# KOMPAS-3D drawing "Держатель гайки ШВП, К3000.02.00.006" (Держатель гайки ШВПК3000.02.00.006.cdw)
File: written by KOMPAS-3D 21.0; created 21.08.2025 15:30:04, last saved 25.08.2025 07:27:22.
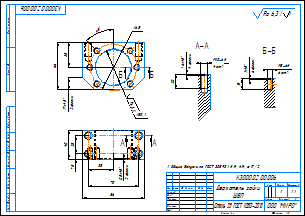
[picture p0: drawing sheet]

Sheet 1: A3, landscape

Document properties: Автор: admin; Знак неуказанной шероховатости: 4; Параметр неуказанной шероховатости: Ra 6,3; Масса: 0.99956

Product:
- Part/product: Держатель гайки ШВП  | designation К3000.02.00.006
    Материал: Сталь 35 ГОСТ 1050-2013 (density 7826 kg/m3)
    Масса: 0.99956

Title block, sheet 1: Наименование: Держатель гайки / ШВП; designation: К3000.02.00.006; Материал: Сталь 35 ГОСТ 1050-2013; Масса: 1; Количество листов документа: 1; organisation: ООО "МИРО"; Форматы листов документа: A3; stored path: C:\Users\ShavarinML\Desktop\Стапель\2D\Держатель гайки ШВПК3000.02.00.006.cdw

Views: Спереди 1, Спереди, Проекционный вид 2, Разрез А-А, Разрез Б-Б, Вид:1
Referenced files in C:\Users\ShavarinML\Desktop\Стапель\Задняя бабака\ШВП\Кронштейн DSG для SFU 3D-модели\: Bracket DSG32H.m3d
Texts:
  Ra 3,2
  Ra 6,3
  Ra 6,3 ( )
  К3000.02.00.006 Держатель гайки ШВП
Dimensions and other numbers on the sheet: 66; 17; 2 фаски; 65; 50,1; 35; 86; 40; 70; 7,5; 25; 0,5; 20; 1,6; 4 фаски; -6H; 10; 4 отв.; 15; 1; 6 фасок; 8; 6 отв.; 1:1

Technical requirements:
  Общие допуски по ГОСТ 30893.1: H14, h14,   IT/2.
